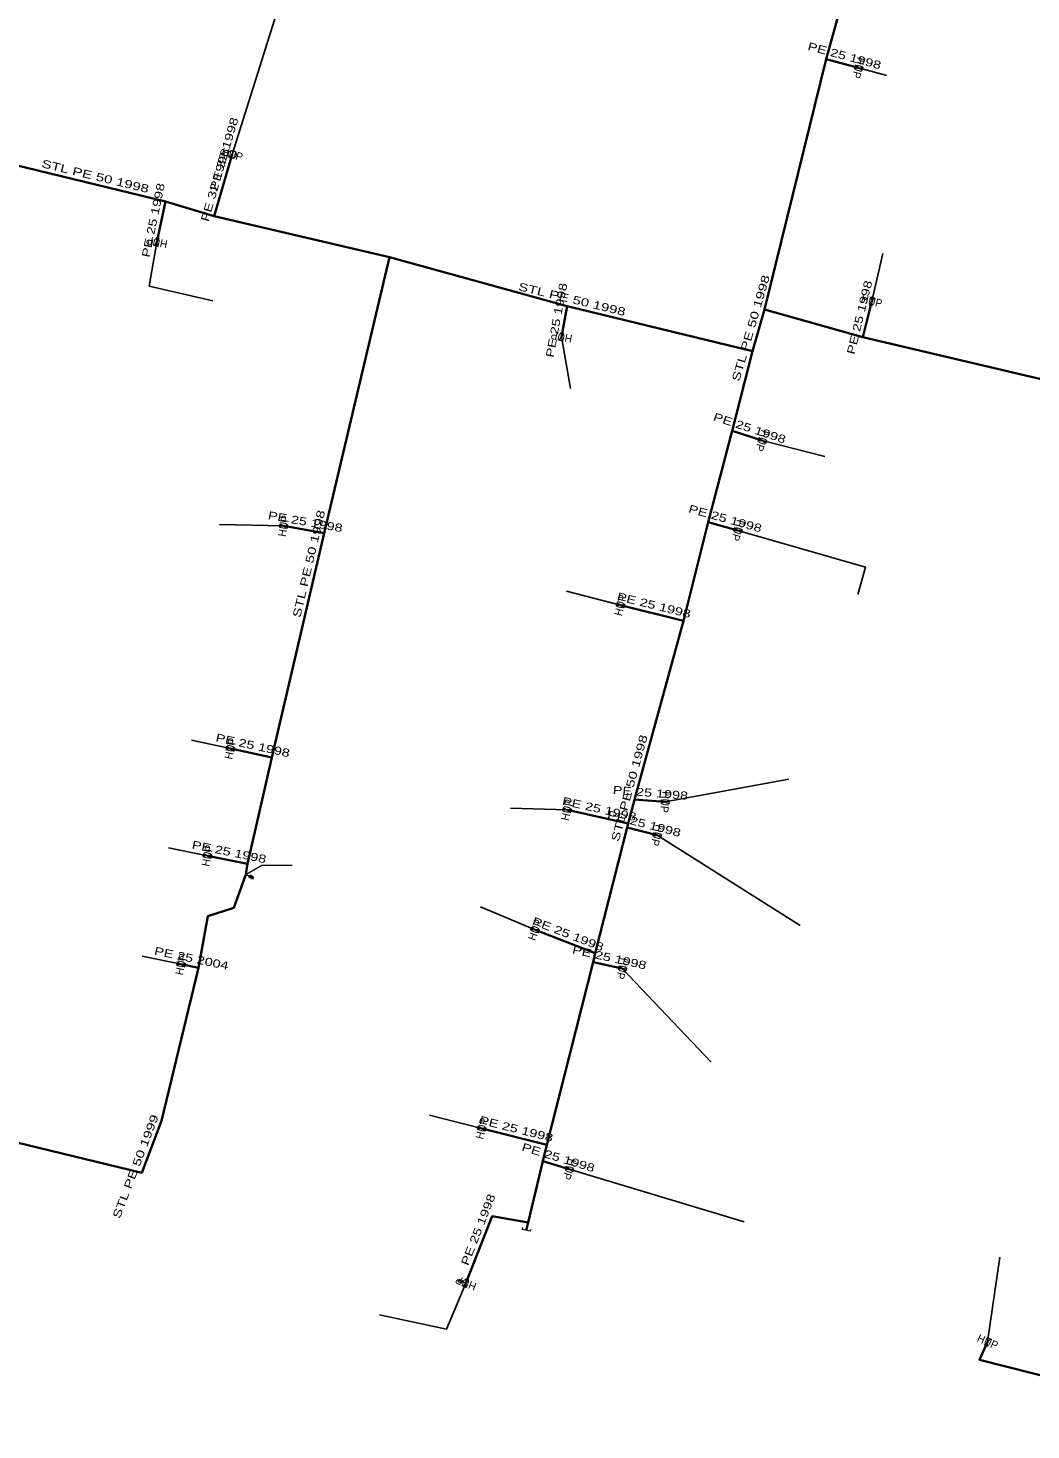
# Model space of a CAD drawing. Extents: x -737484 to -734496, y -1033882 to -1030666.
# Drawn here: x -735874.4 to -735749, y -1032078.7 to -1031903.6 of the extents above; entities that cross this region are included whole.
import ezdxf
from ezdxf.enums import TextEntityAlignment as Align

# ---------------------------------------------------------------- set-up
doc = ezdxf.new("R2010")
doc.units = 0
doc.header["$LTSCALE"] = 0.4
for name, color, linetype, lineweight in [('1', 7, 'Continuous', 13), ('22', 7, 'Continuous', 25), ('5', 7, 'Continuous', 35), ('7', 7, 'Continuous', 35)]:
    doc.layers.add(name, color=color, linetype=linetype, lineweight=lineweight)
doc.layers.add('2', color=7, linetype='Continuous')

msp = doc.modelspace()

# ---------------------------------------------------------------- linework, layer by layer
at = {"layer": '1'}
for p, q in [((-735847.118, -1032009.307), (-735846.68, -1032009.549)), ((-735846.651, -1032009.651), (-735846.345, -1032009.821)), ((-735820.149, -1032060.113), (-735820.476, -1032059.988)), ((-735819.64, -1032060.39), (-735820.106, -1032060.21))]:
    msp.add_line(p, q, dxfattribs=at)
for points in [[(-735769.994, -1031908.476), (-735770.097, -1031908.862), (-735770.96, -1031908.217), (-735771.063, -1031908.603)], [(-735858.178, -1031930.859), (-735858.569, -1031930.776), (-735857.97, -1031929.881), (-735858.361, -1031929.798)], [(-735768.972, -1031937.166), (-735768.583, -1031937.263), (-735769.214, -1031938.136), (-735768.825, -1031938.233)], [(-735807.578, -1031942.697), (-735807.97, -1031942.621), (-735807.387, -1031941.716), (-735807.779, -1031941.64)], [(-735782.049, -1031955.083), (-735782.173, -1031955.463), (-735783, -1031954.774), (-735783.124, -1031955.154)], [(-735842.936, -1031965.887), (-735842.866, -1031965.493), (-735841.951, -1031966.06), (-735841.881, -1031965.666)], [(-735785.092, -1031966.274), (-735785.202, -1031966.659), (-735786.053, -1031965.998), (-735786.163, -1031966.383)], [(-735800.821, -1031975.751), (-735800.724, -1031975.362), (-735799.851, -1031975.993), (-735799.754, -1031975.604)], [(-735849.588, -1031993.69), (-735849.505, -1031993.299), (-735848.61, -1031993.898), (-735848.527, -1031993.507)], [(-735807.501, -1032001.34), (-735807.411, -1032000.95), (-735806.526, -1032001.565), (-735806.436, -1032001.175)], [(-735794.203, -1032000.112), (-735794.238, -1032000.51), (-735795.199, -1032000.025), (-735795.234, -1032000.423)], [(-735795.194, -1032004.355), (-735795.291, -1032004.744), (-735796.164, -1032004.113), (-735796.261, -1032004.502)], [(-735852.456, -1032007.078), (-735852.38, -1032006.686), (-735851.475, -1032007.269), (-735851.399, -1032006.877)], [(-735846.243, -1032009.791), (-735846.316, -1032009.923), (-735846.753, -1032009.68), (-735846.68, -1032009.549)], [(-735846.294, -1032009.805), (-735846.33, -1032009.871), (-735846.702, -1032009.665), (-735846.666, -1032009.599)], [(-735846.243, -1032009.791), (-735846.17, -1032009.66), (-735846.607, -1032009.418), (-735846.68, -1032009.549)], [(-735811.507, -1032016.254), (-735811.364, -1032015.881), (-735810.573, -1032016.612), (-735810.43, -1032016.239)], [(-735855.749, -1032020.64), (-735855.666, -1032020.249), (-735854.771, -1032020.848), (-735854.688, -1032020.457)], [(-735799.548, -1032020.987), (-735799.631, -1032021.378), (-735800.526, -1032020.779), (-735800.609, -1032021.17)], [(-735818.171, -1032041.131), (-735818.074, -1032040.742), (-735817.201, -1032041.373), (-735817.104, -1032040.984)], [(-735806.162, -1032046.103), (-735806.279, -1032046.486), (-735807.118, -1032045.811), (-735807.235, -1032046.194)], [(-735820.573, -1032060.031), (-735820.627, -1032060.171), (-735820.16, -1032060.35), (-735820.106, -1032060.21)], [(-735820.573, -1032060.031), (-735820.519, -1032059.891), (-735820.053, -1032060.07), (-735820.106, -1032060.21)], [(-735820.524, -1032060.01), (-735820.497, -1032059.94), (-735820.101, -1032060.092), (-735820.128, -1032060.163)], [(-735819.629, -1032060.927), (-735820.002, -1032060.784), (-735819.271, -1032059.993), (-735819.644, -1032059.85)], [(-735754.379, -1032067.169), (-735754.013, -1032067.332), (-735754.786, -1032068.083), (-735754.42, -1032068.246)]]:
    msp.add_lwpolyline(points, close=True, dxfattribs=at)
for points in [[(-735847.12, -1032009.31), (-735845.148, -1032008.166), (-735841.351, -1032008.181)], [(-735811.533, -1032053.667), (-735811.593, -1032053.909), (-735812.564, -1032053.668), (-735812.503, -1032053.425)]]:
    msp.add_lwpolyline(points, dxfattribs=at)
msp.add_circle((-735848.8406, -1031919.3591), 0.5, dxfattribs=at)
at = {"layer": '22'}
for p, q in [((-735770.529, -1031908.54), (-735766.984, -1031909.48)), ((-735768.899, -1031937.7), (-735767.509, -1031931.751)), ((-735807.679, -1031942.169), (-735806.568, -1031948.596)), ((-735782.588, -1031955.119), (-735774.775, -1031957.097)), ((-735842.409, -1031965.778), (-735850.422, -1031965.601)), ((-735800.289, -1031975.678), (-735807.055, -1031973.942)), ((-735849.058, -1031993.599), (-735853.942, -1031992.53)), ((-735794.719, -1032000.269), (-735779.263, -1031997.414)), ((-735806.969, -1032001.259), (-735814.057, -1032001.032)), ((-735795.729, -1032004.429), (-735777.845, -1032015.69)), ((-735851.928, -1032006.978), (-735856.829, -1032005.988)), ((-735810.969, -1032016.248), (-735817.821, -1032013.383)), ((-735855.219, -1032020.549), (-735860.113, -1032019.527)), ((-735800.08, -1032021.079), (-735788.952, -1032032.785)), ((-735817.639, -1032041.059), (-735824.176, -1032039.379)), ((-735806.699, -1032046.149), (-735784.833, -1032052.742)), ((-735754.4, -1032067.709), (-735752.873, -1032057.136))]:
    msp.add_line(p, q, dxfattribs=at)
for points in [[(-735848.84, -1031919.359), (-735840.097, -1031891.524), (-735827.134, -1031892.578)], [(-735858.27, -1031930.329), (-735859.216, -1031935.8), (-735851.283, -1031937.663)], [(-735785.629, -1031966.329), (-735769.676, -1031970.946), (-735770.647, -1031974.348)], [(-735819.638, -1032060.39), (-735822.072, -1032066.144), (-735830.41, -1032064.362)]]:
    msp.add_lwpolyline(points, dxfattribs=at)
at = {"layer": '5'}
msp.add_line((-735782.3, -1031938.74), (-735783.81, -1031943.94), dxfattribs=at)
for points in [[(-735755.68, -1031843.84), (-735759.27, -1031851), (-735762.69, -1031864.48), (-735771.82, -1031897.52), (-735773.35, -1031902.95), (-735774.59, -1031907.44), (-735782.3, -1031938.74)], [(-735901.297, -1031909.367), (-735897.21, -1031912.61), (-735887.14, -1031917.65), (-735886.55, -1031917.91), (-735880.41, -1031919.6), (-735857.2, -1031925.23), (-735851.09, -1031927.09), (-735829.2, -1031932.21)], [(-735829.2, -1031932.21), (-735837.34, -1031966.68), (-735843.89, -1031994.73), (-735845.094, -1032000), (-735846.92, -1032007.99), (-735847.12, -1032009.31)], [(-735783.81, -1031943.94), (-735806.96, -1031938.33), (-735829.2, -1031932.21)], [(-735782.3, -1031938.74), (-735770, -1031942.2), (-735743.28, -1031948.46), (-735723.06, -1031952.68), (-735719.26, -1031953.36), (-735691.099, -1031960.091)], [(-735783.81, -1031943.94), (-735786.35, -1031953.88), (-735789.33, -1031965.29), (-735792.43, -1031977.62), (-735798.55, -1031999.96), (-735798.56, -1032000), (-735799.35, -1032002.96), (-735799.46, -1032003.47), (-735803.46, -1032019.15), (-735803.73, -1032020.27), (-735809.51, -1032043.1), (-735810.02, -1032045.14), (-735811.83, -1032052.8), (-735812.079, -1032053.789)], [(-735847.12, -1032009.31), (-735848.66, -1032013.51), (-735851.89, -1032014.55), (-735853.06, -1032021), (-735857.68, -1032040.1), (-735860.16, -1032046.61), (-735883.03, -1032041.05), (-735886.19, -1032040.28), (-735886.95, -1032040.18), (-735898.84, -1032038.48), (-735899.369, -1032038.45)]]:
    msp.add_lwpolyline(points, dxfattribs=at)
at = {"layer": '7'}
for p, q in [((-735774.59, -1031907.44), (-735770.529, -1031908.54)), ((-735851.09, -1031927.09), (-735848.97, -1031919.8)), ((-735848.97, -1031919.8), (-735848.84, -1031919.359)), ((-735857.2, -1031925.23), (-735858.27, -1031930.329)), ((-735806.96, -1031938.33), (-735807.679, -1031942.169)), ((-735770, -1031942.2), (-735768.899, -1031937.7)), ((-735786.35, -1031953.88), (-735782.587, -1031955.119)), ((-735837.34, -1031966.68), (-735842.409, -1031965.777)), ((-735789.33, -1031965.29), (-735785.628, -1031966.329)), ((-735792.43, -1031977.62), (-735800.288, -1031975.678)), ((-735843.89, -1031994.73), (-735849.058, -1031993.599)), ((-735799.35, -1032002.96), (-735806.969, -1032001.258)), ((-735799.46, -1032003.47), (-735795.728, -1032004.429)), ((-735846.92, -1032007.99), (-735851.928, -1032006.978)), ((-735803.46, -1032019.15), (-735810.969, -1032016.247)), ((-735853.06, -1032021), (-735855.219, -1032020.549)), ((-735803.73, -1032020.27), (-735800.079, -1032021.079)), ((-735809.51, -1032043.1), (-735817.638, -1032041.058)), ((-735810.02, -1032045.14), (-735806.699, -1032046.149))]:
    msp.add_line(p, q, dxfattribs=at)
for points in [[(-735798.55, -1031999.96), (-735798.055, -1032000), (-735794.719, -1032000.268)], [(-735811.83, -1032052.8), (-735816.36, -1032052.02), (-735819.637, -1032060.389)], [(-735720.82, -1032078.73), (-735755.42, -1032069.96), (-735754.4, -1032067.708)]]:
    msp.add_lwpolyline(points, dxfattribs=at)

# ---------------------------------------------------------------- texts
at = {"layer": '2', "width": 0.95}
for rotation, p in [(255, (-735771.0113, -1031908.4101)), (344, (-735848.9773, -1031919.8388)), (168, (-735858.1655, -1031929.8392)), (346, (-735769.0195, -1031938.185)), (169, (-735807.5831, -1031941.6779)), (252, (-735783.062, -1031954.964)), (80, (-735841.9156, -1031965.8633)), (254, (-735786.1078, -1031966.1907)), (76, (-735799.802, -1031975.7985)), (78, (-735848.5682, -1031993.7025)), (265, (-735795.2167, -1032000.2239)), (77, (-735806.4815, -1032001.37)), (256, (-735796.213, -1032004.3075)), (79, (-735851.4369, -1032007.0729)), (69, (-735810.5017, -1032016.4257)), (78, (-735854.7292, -1032020.6525)), (258, (-735800.5678, -1032020.9745)), (76, (-735817.152, -1032041.1785)), (253, (-735807.1768, -1032046.0023)), (159, (-735819.4573, -1032059.9217)), (336, (-735754.6029, -1032068.1647))]:
    msp.add_text('HUP', height=1, rotation=rotation, dxfattribs=at).set_placement(p, align=Align.CENTER)
at = {"layer": '5', "width": 1.4}
for s, rotation, p in [('STL PE 50 1998', 346.365, (-735866.0744, -1031922.5619)), ('STL PE 50 1998', 73.808, (-735783.5344, -1031941.1999)), ('STL PE 50 1998', 346.378, (-735806.4758, -1031937.9325)), ('STL PE 50 1998', 76.856, (-735838.7726, -1031970.6187)), ('STL PE 50 1998', 74.68, (-735798.7119, -1031998.6581)), ('STL PE 50 1999', 69.146, (-735860.4593, -1032045.9905))]:
    msp.add_text(s, height=1, rotation=rotation, dxfattribs=at).set_placement(p, align=Align.CENTER)
at = {"layer": '7', "width": 1.35}
for s, rotation, p in [('PE 25 1998', 344.844, (-735772.4282, -1031907.5066)), ('PE 32 1998', 73.575, (-735849.3841, -1031919.4379)), ('PE 32 1998', 73.785, (-735850.51, -1031923.3051)), ('PE 25 1998', 78.149, (-735858.2234, -1031927.6762)), ('PE 25 1998', 79.392, (-735807.8106, -1031940.157)), ('PE 25 1998', 76.252, (-735769.9346, -1031939.8308)), ('PE 25 1998', 341.775, (-735784.3119, -1031954.0238)), ('PE 25 1998', 349.899, (-735839.7862, -1031965.7357)), ('PE 25 1998', 344.323, (-735787.3436, -1031965.3278)), ('PE 25 1998', 346.118, (-735796.2385, -1031976.1633)), ('PE 25 1998', 347.656, (-735846.3669, -1031993.676)), ('PE 25 1998', 347.408, (-735803.05, -1032001.6204)), ('PE 25 1998', 355.407, (-735796.594, -1031999.6153)), ('PE 25 1998', 345.589, (-735797.4689, -1032003.4644)), ('PE 25 1998', 348.576, (-735849.3245, -1032006.9935)), ('PE 25 1998', 338.863, (-735807.0338, -1032017.2315)), ('PE 25 2004', 348.201, (-735854.0367, -1032020.2842)), ('PE 25 1998', 347.506, (-735801.7957, -1032020.1862)), ('PE 25 1998', 345.897, (-735813.4518, -1032041.5933)), ('PE 25 1998', 343.1, (-735808.2134, -1032045.1661)), ('PE 25 1998', 68.616, (-735817.6252, -1032053.8813))]:
    msp.add_text(s, height=1, rotation=rotation, dxfattribs=at).set_placement(p, align=Align.CENTER)

doc.saveas('drawing.dxf')
